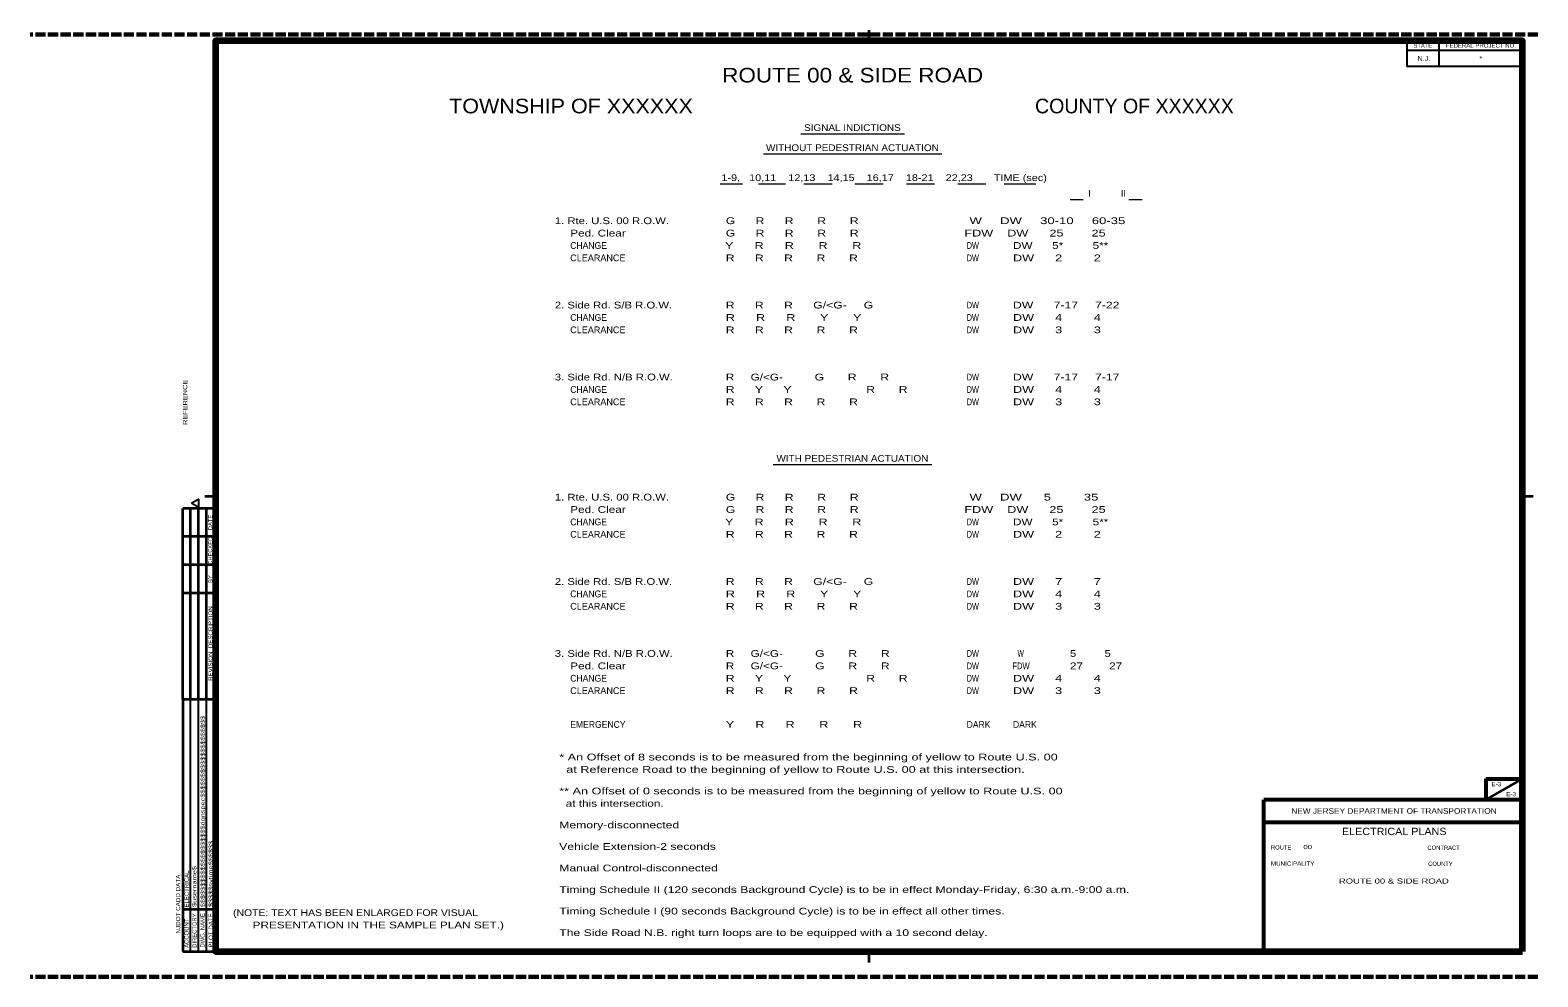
# Model space of a CAD drawing. Extents: x 168203 to 169863, y 223196 to 223870.
# Drawn here: x 169095.8 to 169364, y 223196.5 to 223364.9 of the extents above; entities that cross this region are included whole.
import ezdxf
from ezdxf.enums import TextEntityAlignment as Align

# ---------------------------------------------------------------- set-up
doc = ezdxf.new("R2010")
doc.units = 0
doc.header["$LTSCALE"] = 0.3
doc.linetypes.add('LONG_DASHED', pattern=[7.5, 6, -1.5])
doc.layers.add('1', color=7, linetype='Continuous', lineweight=13)
doc.layers.add('25', color=7, linetype='Continuous', lineweight=35)

msp = doc.modelspace()

# ---------------------------------------------------------------- linework, layer by layer
at = {"layer": '1', "linetype": 'LONG_DASHED', "lineweight": 60}
for p, q in [((169364.0333, 223364.1089), (169095.8093, 223364.1089)), ((169364.0333, 223196.4689), (169095.8093, 223196.4689))]:
    msp.add_line(p, q, dxfattribs=at)
at = {"layer": '1', "lineweight": 35}
for p, q in [((169245.0333, 223364.8589), (169245.0333, 223362.9689)), ((169126.8633, 223281.9689), (169128.7833, 223281.9689)), ((169361.2833, 223281.9689), (169363.2033, 223281.9689)), ((169122.946, 223245.8604), (169128.7833, 223245.8604)), ((169122.946, 223245.8604), (169122.946, 223200.9689)), ((169122.946, 223208.505), (169128.7833, 223208.505)), ((169122.946, 223200.9689), (169128.7833, 223200.9689)), ((169245.0333, 223200.9689), (169245.0333, 223199.0489))]:
    msp.add_line(p, q, dxfattribs=at)
at = {"layer": '1', "lineweight": 25}
for p, q in [((169340.7093, 223362.9689), (169340.7093, 223358.3969)), ((169361.2833, 223361.2544), (169340.7093, 223361.2544)), ((169346.4243, 223362.9689), (169346.4243, 223358.3969)), ((169361.2833, 223358.3969), (169340.7093, 223358.3969)), ((169124.3646, 223200.9689), (169124.3646, 223245.8604)), ((169125.7833, 223200.9689), (169125.7833, 223245.8604)), ((169127.1658, 223200.9689), (169127.1658, 223245.8604))]:
    msp.add_line(p, q, dxfattribs=at)
at = {"layer": '1'}
for p, q in [((169232.9075, 223346.4307), (169251.3817, 223346.4307)), ((169226.2774, 223342.8551), (169258.0118, 223342.8551)), ((169218.5477, 223337.5271), (169222.5417, 223337.5271)), ((169225.3687, 223337.5271), (169230.1789, 223337.5271)), ((169233.4202, 223337.5271), (169238.4994, 223337.5271)), ((169242.5427, 223337.5271), (169247.5348, 223337.5271)), ((169251.7296, 223337.5271), (169256.7245, 223337.5271)), ((169260.8566, 223337.5271), (169265.8572, 223337.5271)), ((169269.0681, 223337.5271), (169274.7201, 223337.5271)), ((169280.8095, 223334.7193), (169283.1467, 223334.7193)), ((169291.2843, 223334.7193), (169293.6215, 223334.7193)), ((169227.9711, 223287.6031), (169256.2091, 223287.6031))]:
    msp.add_line(p, q, dxfattribs=at)
at = {"layer": '1', "lineweight": 158}
msp.add_lwpolyline([(169361.2833, 223200.9689), (169361.2833, 223362.9689), (169128.7833, 223362.9689), (169128.7833, 223200.9689)], close=True, dxfattribs=at)
at = {"layer": '25'}
for p, q in [((169128.7833, 223279.8002), (169122.946, 223279.8002)), ((169122.946, 223245.8604), (169122.946, 223279.8002)), ((169124.3646, 223245.8604), (169124.3646, 223279.8002)), ((169125.7833, 223245.8604), (169125.7833, 223279.8002)), ((169127.1658, 223245.8604), (169127.1658, 223279.8002)), ((169128.7833, 223274.7671), (169122.946, 223274.7671)), ((169128.7833, 223269.7339), (169122.946, 223269.7339)), ((169128.7833, 223264.7008), (169122.946, 223264.7008)), ((169128.5845, 223264.7008), (169127.1658, 223264.7008)), ((169354.7833, 223227.9689), (169361.2833, 223231.7189))]:
    msp.add_line(p, q, dxfattribs=at)
at = {"layer": '25', "lineweight": 53}
for p, q in [((169354.7833, 223231.7189), (169361.2833, 223231.7189)), ((169354.7833, 223231.7189), (169354.7833, 223227.9689)), ((169315.2833, 223200.9689), (169315.2833, 223227.9689)), ((169361.2833, 223227.9689), (169315.2833, 223227.9689)), ((169315.2833, 223223.9689), (169361.2833, 223223.9689))]:
    msp.add_line(p, q, dxfattribs=at)
at = {"layer": '25', "lineweight": 25}
msp.add_lwpolyline([(169125.7923, 223281.4267), (169124.5725, 223280.7219), (169125.7923, 223280.0171)], close=True, dxfattribs=at)

# ---------------------------------------------------------------- texts
at = {"layer": '1'}
for s, height, width, p in [('STATE', 0.7315, 1.05, (169343.5668, 223361.7459)), ('FEDERAL PROJECT NO.', 0.7315, 1.1, (169353.9028, 223361.7459)), ('ROUTE 00 & SIDE ROAD', 2.6, 1.15, (169242.1445, 223355.5529)), ('N.J.', 0.9144, 1.05, (169343.7648, 223359.3684)), ('TOWNSHIP OF XXXXXX', 2.6, 1.1, (169192.0279, 223350.0663)), ('SIGNAL INDICTIONS', 1.202, 1.1, (169242.0901, 223346.9191)), ('WITHOUT PEDESTRIAN ACTUATION', 1.202, 1.1, (169242.0901, 223343.3435)), ('WITH PEDESTRIAN ACTUATION', 1.202, 1.1, (169242.0901, 223288.0915))]:
    msp.add_text(s, height=height, dxfattribs=dict(at, width=width)).set_placement(p, align=Align.CENTER)
for s, height, p in [('*', 0.9144, (169353.9028, 223359.3599)), ('COUNTY OF XXXXXX', 2.6, (169292.2613, 223350.0663)), ('I            II', 1.202, (169287.4098, 223335.229))]:
    msp.add_text(s, height=height, dxfattribs=at).set_placement(p, align=Align.CENTER)
for s, width, p in [('1-9,   10,11    12,13    14,15    16,17    18-21    22,23       TIME (sec)', 1.2, (169218.7869, 223338.0155)), ('1. Rte. U.S. 00 R.O.W.', 1.25, (169189.1475, 223330.358)), ('G      R      R       R       R', 1.35, (169219.5657, 223330.358)), ('W     DW     30-10     60-35', 1.45, (169262.9244, 223330.358)), ('Ped. Clear', 1.3, (169191.8917, 223328.1562)), ('G      R      R       R       R', 1.35, (169219.5657, 223328.1562)), ('FDW    DW      25        25', 1.4, (169262.0098, 223328.1562)), ('CHANGE', 0.95, (169191.8917, 223325.9544)), ('Y      R      R       R       R', 1.4, (169219.4234, 223325.9544)), ('DW', 0.75, (169262.4156, 223325.9544)), ('DW      5*         5**', 1.3, (169270.659, 223325.9544)), ('R      R      R       R       R', 1.35, (169219.5657, 223323.7526)), ('DW', 0.75, (169262.4156, 223323.7526)), ('DW      2         2', 1.4, (169270.659, 223323.7526)), ('2. Side Rd. S/B R.O.W.', 1.25, (169189.1475, 223315.3522)), ('R      R      R      G/<G-     G', 1.35, (169219.5657, 223315.3522)), ('DW', 0.75, (169262.4156, 223315.3522)), ('DW      7-17     7-22', 1.35, (169270.659, 223315.3522)), ('CHANGE', 0.95, (169191.8917, 223313.1504)), ('R      R      R       Y       Y', 1.4, (169219.5657, 223313.1504)), ('DW', 0.75, (169262.4156, 223313.1504)), ('DW      4         4', 1.4, (169270.659, 223313.1504)), ('R      R      R       R       R', 1.35, (169219.5657, 223310.9486)), ('DW', 0.75, (169262.4156, 223310.9486)), ('DW      3         3', 1.4, (169270.659, 223310.9486)), ('3. Side Rd. N/B R.O.W.', 1.25, (169189.1475, 223302.5482)), ('R     G/<G-', 1.3, (169219.5657, 223302.5482)), ('G       R       R', 1.35, (169235.3664, 223302.5494)), ('DW', 0.75, (169262.4156, 223302.5482)), ('DW      7-17     7-17', 1.35, (169270.659, 223302.5482)), ('CHANGE', 0.95, (169191.8917, 223300.3464)), ('R      Y      Y', 1.35, (169219.5657, 223300.3464)), ('R      R      R       R       R', 1.35, (169219.5657, 223298.1446)), ('R       R', 1.35, (169244.5477, 223300.3464)), ('DW', 0.75, (169262.4156, 223300.3464)), ('DW', 0.75, (169262.4156, 223298.1446)), ('DW      4         4', 1.4, (169270.659, 223300.3464)), ('DW      3         3', 1.4, (169270.659, 223298.1446)), ('1. Rte. U.S. 00 R.O.W.', 1.25, (169189.1475, 223281.1929)), ('G      R      R       R       R', 1.35, (169219.5657, 223281.1929)), ('W     DW      5         35', 1.45, (169262.9244, 223281.1929)), ('CHANGE', 0.95, (169191.8917, 223276.7893)), ('Ped. Clear', 1.3, (169191.8917, 223278.9911)), ('Y      R      R       R       R', 1.4, (169219.4234, 223276.7893)), ('G      R      R       R       R', 1.35, (169219.5657, 223278.9911)), ('FDW    DW      25        25', 1.4, (169262.0098, 223278.9911)), ('DW', 0.75, (169262.4156, 223276.7893)), ('DW      5*         5**', 1.3, (169270.659, 223276.7893)), ('R      R      R       R       R', 1.35, (169219.5657, 223274.5875)), ('DW', 0.75, (169262.4156, 223274.5875)), ('DW      2         2', 1.4, (169270.659, 223274.5875)), ('2. Side Rd. S/B R.O.W.', 1.25, (169189.1475, 223266.1871)), ('R      R      R      G/<G-     G', 1.35, (169219.5657, 223266.1871)), ('DW', 0.75, (169262.4156, 223266.1871)), ('DW      7         7', 1.4, (169270.659, 223266.1871)), ('CHANGE', 0.95, (169191.8917, 223263.9853)), ('R      R      R       Y       Y', 1.4, (169219.5657, 223263.9853)), ('DW', 0.75, (169262.4156, 223263.9853)), ('DW      4         4', 1.4, (169270.659, 223263.9853)), ('R      R      R       R       R', 1.35, (169219.5657, 223261.7835)), ('DW', 0.75, (169262.4156, 223261.7835)), ('DW      3         3', 1.4, (169270.659, 223261.7835)), ('3. Side Rd. N/B R.O.W.', 1.25, (169189.1475, 223253.3831)), ('R     G/<G-', 1.3, (169219.5657, 223253.3831)), ('G       R       R', 1.35, (169235.4594, 223253.3826)), ('DW', 0.75, (169262.4156, 223253.3831)), ('W', 0.6, (169271.4591, 223253.3831)), ('5         5', 1.25, (169280.7938, 223253.3831)), ('Ped. Clear', 1.3, (169191.8917, 223251.1813)), ('R     G/<G-', 1.3, (169219.5657, 223251.1813)), ('G       R       R', 1.35, (169235.4594, 223251.1808)), ('DW', 0.75, (169262.4156, 223251.1813)), ('FDW', 0.85, (169270.5212, 223251.1813)), ('27        27', 1.3, (169280.7938, 223251.1813)), ('CHANGE', 0.95, (169191.8917, 223248.9795)), ('R      Y      Y', 1.35, (169219.5657, 223248.9795)), ('R       R', 1.35, (169244.5477, 223248.9795)), ('DW', 0.75, (169262.4156, 223248.9795)), ('DW      4         4', 1.4, (169270.659, 223248.9795)), ('R      R      R       R       R', 1.35, (169219.5657, 223246.7777)), ('DW', 0.75, (169262.4156, 223246.7777)), ('DW      3         3', 1.4, (169270.659, 223246.7777)), ('EMERGENCY', 0.95, (169191.8917, 223240.7623)), ('Y      R      R       R       R', 1.4, (169219.5657, 223240.7623)), ('DARK', 0.95, (169262.4156, 223240.7623)), ('DARK', 0.95, (169270.659, 223240.7623)), ('* An Offset of 8 seconds is to be measured from the beginning of yellow to Route U.S. 00', 1.4, (169189.9332, 223234.957)), ('  at Reference Road to the beginning of yellow to Route U.S. 00 at this intersection.', 1.4, (169189.9332, 223232.7552)), ('** An Offset of 0 seconds is to be measured from the beginning of yellow to Route U.S. 00', 1.4, (169189.9332, 223228.9226)), ('  at this intersection.', 1.3, (169189.9332, 223226.7208)), ('Memory-disconnected', 1.35, (169189.9332, 223222.8882)), ('Vehicle Extension-2 seconds', 1.35, (169189.9332, 223219.0556)), ('Manual Control-disconnected', 1.35, (169189.9332, 223215.223)), ('Timing Schedule II (120 seconds Background Cycle) is to be in effect Monday-Friday, 6:30 a.m.-9:00 a.m.', 1.35, (169189.9332, 223211.3904)), ('(NOTE: TEXT HAS BEEN ENLARGED FOR VISUAL', 1.15, (169131.9116, 223207.2864)), ('Timing Schedule I (90 seconds Background Cycle) is to be in effect all other times.', 1.35, (169189.9332, 223207.5578)), ('      PRESENTATION IN THE SAMPLE PLAN SET.)', 1.3, (169131.9116, 223205.0846)), ('The Side Road N.B. right turn loops are to be equipped with a 10 second delay.', 1.35, (169189.9332, 223203.7252))]:
    msp.add_text(s, height=1.202, dxfattribs=dict(at, width=width)).set_placement(p)
for p in [(169191.8917, 223323.7526), (169191.8917, 223310.9486), (169191.8917, 223298.1446), (169191.8917, 223274.5875), (169191.8917, 223261.7835), (169191.8917, 223246.7777)]:
    msp.add_text('CLEARANCE', height=1.202, dxfattribs=at).set_placement(p)
for s, height, width, p in [('REFERENCE                                                              ', 0.75, 1.3, (169123.7433, 223294.6289)), ('$$$$$$$$$$$$$$$$$$$$dgnspec$$$$$$$$$$$$$$$$$$$$', 0.7526, 1.3, (169126.8767, 223208.8484)), ('$$$$$sytime$$$$$$', 0.7526, 1.3, (169128.2953, 223208.8846)), ('$username$', 0.7526, 1.3, (169125.3947, 223208.8936)), ('NJDOT CADD DATA', 0.759, 1.1, (169122.5032, 223204.1677)), ('PLOT DATE', 0.7499, 1.1, (169128.3134, 223201.6737))]:
    msp.add_text(s, height=height, rotation=90, dxfattribs=dict(at, width=width)).set_placement(p)
for s, height, p in [('ELECTRICAL', 0.768, (169124.0393, 223208.8213)), ('ACCOUNT', 0.7589, (169124.0032, 223201.6285)), ('DIRECTORY', 0.75, (169125.4128, 223201.6376)), ('DWG. NAME', 0.75, (169126.8496, 223201.6828))]:
    msp.add_text(s, height=height, rotation=90, dxfattribs=at).set_placement(p)
at = {"layer": '25'}
msp.add_text('DATE', height=0.741, rotation=90, dxfattribs=at).set_placement((169128.214, 223277.2902), align=Align.CENTER)
for s, width, p in [('CHECKED', 0.9, (169128.214, 223272.2564)), ('BY', 0.9, (169128.214, 223267.2199)), ('REVISION  DESCRIPTION', 1.1, (169128.2502, 223255.7491))]:
    msp.add_text(s, height=0.741, rotation=90, dxfattribs=dict(at, width=width)).set_placement(p, align=Align.CENTER)
for s, height, width, p in [('E-3', 0.75, 1.1, (169356.6606, 223230.3729)), ('E-3', 0.75, 1.1, (169359.2798, 223228.5835)), ('NEW JERSEY DEPARTMENT OF TRANSPORTATION', 1, 1.1, (169338.4408, 223225.4689)), ('ELECTRICAL PLANS', 1.3, 1.1, (169338.488, 223221.6856)), ('             ROUTE 00 & SIDE ROAD            ', 0.9, 1.4, (169338.181, 223213.0589))]:
    msp.add_text(s, height=height, dxfattribs=dict(at, width=width)).set_placement(p, align=Align.CENTER)
for s, width, p in [('ROUTE', 0.95, (169316.5533, 223219.1189)), ('00                        ', 1.4, (169322.3133, 223219.1789)), ('MUNICIPALITY', 1.1, (169316.5533, 223216.2389))]:
    msp.add_text(s, height=0.75, dxfattribs=dict(at, width=width)).set_placement(p)
for s, p in [('CONTRACT', (169344.3933, 223219.0589)), ('COUNTY', (169344.5133, 223216.2089))]:
    msp.add_text(s, height=0.75, dxfattribs=at).set_placement(p)

doc.saveas('drawing.dxf')
